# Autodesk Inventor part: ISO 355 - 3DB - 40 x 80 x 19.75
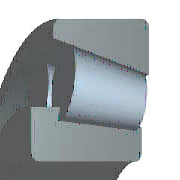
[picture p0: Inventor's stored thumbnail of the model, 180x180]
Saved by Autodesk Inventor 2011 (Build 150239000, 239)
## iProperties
IsCustomPart: 0
Created: 2009-02
Part Number: ISO 355 - 3DB - 40 x 80 x 19.75
Material: Steel, Mild
Description: Metric Tapered Roller Bearings
Document SubType Name: Modeling
Standard: ISO 355
Designer: 904Chiaki
Standard Revision: First edition 1977-05-01
Standards Organization: ISO
Language: en-US
Size Designation: 3DB - 40 x 80 x 19.75
Categories: <MemberInstance><Categories><Category DisplayName="Shaft Parts" InternalName="7f7aeb1f-a693-4053-b835-cee3144e0d98" Mnemonic="SHFT"><Category DisplayName="Beari
Density: 1 g/cm^3
Author: 904Chiaki
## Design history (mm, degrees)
revolve "Body" stored, may be unused: angle "d50" = 90 deg
revolve "Roller" stored, may be unused: angle "d53" = 90 deg
pattern_circular "Rollers" dims angle "d19" = 360 deg
body "Solid1"
sketch "Sketch"
  geometry: L1 (5.768, 31.709)-(6.48, 36.183); L2 (3.75, 36.865)-(19.75, 32.865); L3 (18.277, 33.233)-(17.732, 29.806); L4 (5.768, 31.709)-(17.732, 29.806); L5 (5.768, 31.709)-(5.057, 27.235); L6 (5.057, 27.235)-(17.187, 26.379); L7 (17.187, 26.379)-(17.732, 29.806); L8 (0, 0)-(0, 20); L9 (0, 0)-(18, 0); L10 (17.265, 26.872)-(18, 26.872); L11 (18, 26.872)-(18, 20); L12 (18, 20)-(0, 20); L13 (0, 29.206)-(5.37, 29.206); L14 (0, 29.206)-(0, 20); L15 (19.75, 32.865)-(19.75, 40); L16 (19.75, 40)-(3.75, 40); L17 (3.75, 40)-(3.75, 36.865); L18 (11.75, 30.758)-(12.378, 34.708); L19 (3.75, 36.865)-(19.75, 32.865); L20 (3.75, 36.865)-(3.75, 36.865); L21 (19.75, 32.865)-(19.75, 32.865); L22 (12.378, 34.708)-(12.378, 34.708); L23 (17.187, 26.38)-(5.057, 27.236)
  constraints: 46 end point, 10 parallel, 9 point on line, 5 perpendicular, 2 collinear, 1 midpoint, 1 vertical, 3 other
  dimensions: "d1" = 12.16 distance of L5.end L6.end (= 0.76 x KAB); "d2" = 16 distance of L15.end L16.end (= KAB); "d3" = 40 diameter of L12 L9 (= WD); "d5" = 80 diameter of L16 L9 (= BD); "d7" = 65.73 diameter of L2.end L9 (= BBB); "d8" = 18 distance of L11.end L8.end (= KB1); "d9" = 19.75 distance between parallel lines of L14 L15 (= KB); "d10" = 14.036 deg angle of L2 L13 (= BBA); "d11" = 5 deg angle of L2 L4; "d12" = 4 distance of L18.end L18.start (= -0.1 x WD + 0.1 x BD); "d13" = 8 distance from line of L15 L18.start (= 0.5 x KAB); "d14" = 1.97044 distance from line of L13 L5.end (computed from BBB, KAB, BBA, BD, WD); "d15" = 0.49261 distance from line of L10 L6.end (computed from BBB, KAB, BBA, BD, WD); "d27" = 4.0001 distance of L18.start L22.end (computed from d12); "d66" = 0.001 distance between parallel lines of L6 L23
fillet "Fillet1" dims "d16" = 1.5 (= KR3S), "d17" = 1.5 (= KR1S)
other parameters: "WD" = 40 [user parameter; used in 6 equation terms], "BD" = 80 [user parameter; used in 6 equation terms], "KB" = 19.75 [user parameter; used in 1 equation term], "KB1" = 18 [user parameter; used in 1 equation term], "KR1S" = 1.5 [user parameter; used in 1 equation term], "KR3S" = 1.5 [user parameter; used in 1 equation term], "BBA" = 14.036 deg [user parameter; used in 4 equation terms], "BBB" = 65.73 [user parameter; used in 4 equation terms], "KAB" = 16 [user parameter; used in 6 equation terms], "d22" = 0, "d23" = 0, "d24" = 0, "d25" = 0, "d26" = 0, "BC0" = 3.8e+07 [user parameter], "BC" = 5.1e+07 [user parameter]
